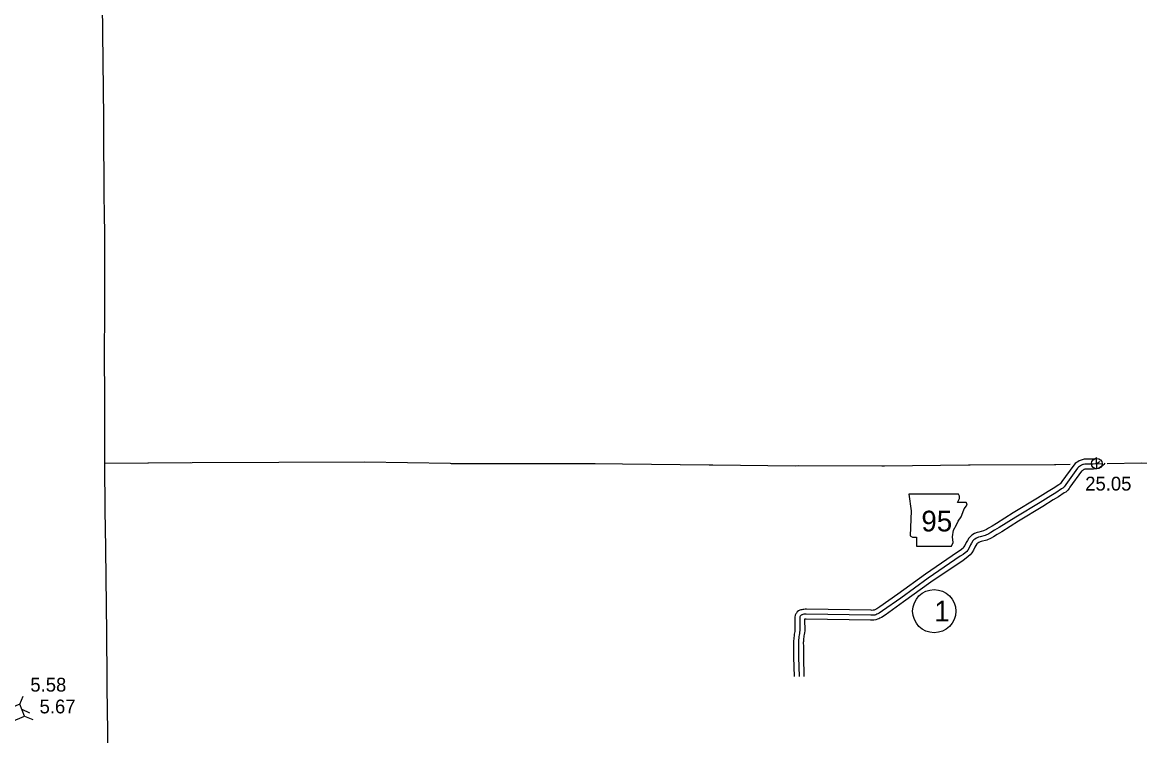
# Model space of a CAD drawing. Extents: x -83719 to 153526, y -11835 to 11446.
# Drawn here: x -664 to 475, y 2059 to 2786 of the extents above; entities that cross this region are included whole.
import ezdxf

# ---------------------------------------------------------------- set-up
doc = ezdxf.new("R2010")
doc.units = 0
for name, color, linetype in [('Level 10', 7, 'Continuous'), ('Level 2', 7, 'Continuous'), ('Level 20', 7, 'Continuous'), ('Level 21', 7, 'Continuous'), ('Level 25', 7, 'Continuous'), ('Level 26', 7, 'Continuous'), ('Level 27', 7, 'Continuous'), ('Level 58', 7, 'Continuous'), ('Level 59', 7, 'Continuous')]:
    doc.layers.add(name, color=color, linetype=linetype)

msp = doc.modelspace()

# ---------------------------------------------------------------- linework, layer by layer
at = {"layer": 'Level 10'}
for points in [[(431.4, 2342.7), (431.3, 2342.6), (431.1, 2342.3), (430.8, 2342), (430.6, 2341.8), (430.3, 2341.6), (429.8, 2341.4), (428.9, 2341), (427.4, 2340.8), (418.4, 2340.8), (416.3, 2340.3), (415.5, 2340), (414.5, 2339.6), (413.3, 2339.1), (412, 2338.3), (410.7, 2337.4), (409.3, 2336.3), (407.9, 2334.9), (395.7, 2318), (395, 2317), (394.2, 2316), (393.5, 2315.3), (392.6, 2314.7), (387, 2310.9), (381.8, 2307.9), (370.9, 2301)], [(439.6, 2336.9), (438.5, 2335.5), (437.4, 2334.5), (436.7, 2333.9), (435.4, 2333), (434.3, 2332.4), (432.3, 2331.5), (430.9, 2331.1), (427.8, 2330.8), (419.6, 2330.8), (419.2, 2330.7), (419, 2330.7), (418.5, 2330.4), (418, 2330.2), (417.3, 2329.8), (416.6, 2329.3), (415.9, 2328.8), (415.6, 2328.5), (403.9, 2312.4), (403.2, 2311.1), (401.7, 2309.3), (399.8, 2307.4), (398.1, 2306.4), (392.3, 2302.4), (387, 2299.3), (376.2, 2292.6)], [(371, 2301.1), (346.1, 2286), (329.2, 2275.3), (324.6, 2272.7), (320.8, 2270.4), (319, 2269.3), (315.7, 2267.8), (311.2, 2266.5), (309.4, 2266.1), (306.5, 2265), (304, 2263.4), (302.4, 2262), (301, 2260.5), (299.5, 2257.9), (298.3, 2256), (296.7, 2252.9), (295.6, 2251), (295, 2250.2), (292.2, 2247.9), (289.4, 2246), (256.6, 2223.6), (228.5, 2203.4), (210.2, 2190.3), (207, 2188.3), (205.8, 2187.7), (204.9, 2187.2), (204.2, 2187), (203.9, 2186.9), (203.2, 2186.8), (202.3, 2186.7), (201.3, 2186.8), (135.3, 2187.9), (133.9, 2187.9), (132.8, 2187.7), (131.8, 2187.7), (130.7, 2187.4), (129.7, 2187.2), (128.7, 2186.9), (127.4, 2186.2), (126, 2185.1), (125.1, 2184), (124.6, 2183.2), (124, 2181.8), (123.5, 2179.9), (123.5, 2178), (123.5, 2166.5), (123.4, 2165.3), (123.2, 2163.8), (122.9, 2162.3), (122.7, 2160.7), (122.5, 2158.8), (122.4, 2157.2), (122.3, 2156.1), (122.1, 2154.6), (122.1, 2152.1), (122.2, 2150.9), (122.3, 2139), (122.8, 2119.3)], [(376.2, 2292.5), (351.4, 2277.5), (334.4, 2266.8), (329.7, 2264.1), (325.9, 2261.8), (323.5, 2260.4), (319.1, 2258.4), (313.6, 2256.8), (312.3, 2256.5), (311, 2256), (309.9, 2255.4), (309.4, 2254.9), (309.1, 2254.5), (308, 2252.7), (307, 2251.1), (305.5, 2248.1), (303.9, 2245.5), (302.3, 2243.3), (298.2, 2239.8), (295, 2237.7), (262.3, 2215.4), (234.4, 2195.3), (215.7, 2182), (211.9, 2179.6), (210.3, 2178.8), (209.1, 2178.2), (207.8, 2177.6), (206, 2177), (204.1, 2176.8), (202.1, 2176.7), (200.8, 2176.8), (135.2, 2177.9), (134.4, 2177.9), (133.8, 2177.8), (133.5, 2177.8), (133.6, 2165.8), (133.3, 2163.9), (133, 2162.1), (132.8, 2160.7), (132.6, 2159.5), (132.5, 2158.1), (132.4, 2156.5), (132.3, 2155), (132.1, 2153.9), (132.1, 2152.5), (132.2, 2151.4), (132.3, 2139.2), (132.8, 2119.3)]]:
    msp.add_lwpolyline(points, dxfattribs=at)
at = {"layer": 'Level 2'}
for points in [[(-580, 2561.9), (-580.3, 2599.4), (-580.4, 2601.5), (-581, 2687.4), (-580.9, 2688.9), (-581.9, 2775.5), (-581.8, 2776.3), (-583, 2861.2), (-494.6, 2861), (-488.5, 2860.9), (-405.1, 2861.7), (-404.8, 2950.1), (-404.3, 3038.9), (-405.8, 3126.3), (-407.1, 3213), (-407.7, 3300.1), (-408, 3324.7)], [(-579.4, 2288.6), (-579.9, 2336.5), (-580, 2424.6), (-580.2, 2426.1), (-579.8, 2512.4), (-579.9, 2513.7), (-580, 2561.9)], [(-579.4, 2288.6), (-579.9, 2336.5), (-580, 2398.3)], [(-79.9, 2336), (-140.3, 2336.2), (-226.6, 2336.2), (-227.5, 2336.3), (-315.3, 2337.7), (-402.6, 2337.4), (-490.9, 2337.1), (-579.9, 2336.5)], [(-492.3, 2337.1), (-579.9, 2336.5)], [(404.3, 2335.4), (389.6, 2335.1), (388.3, 2335.2), (302.3, 2334.7), (300.5, 2334.8), (214.8, 2333.8), (212.2, 2333.8), (127, 2334), (124.3, 2333.7), (39.9, 2334.6), (36.1, 2334.7), (-52.2, 2335.7), (-79.9, 2336)], [(541.2, 2336.4), (476.8, 2336.7), (441.8, 2336)], [(-576.6, 2016.4), (-576.9, 2073.5), (-577, 2075.2), (-577.8, 2161.3), (-577.8, 2163), (-578.8, 2249), (-578.7, 2250.7), (-579.4, 2288.6)], [(-576.6, 2015.1), (-576.9, 2073.5), (-577, 2075.2), (-577.8, 2161.3), (-577.8, 2163), (-578.8, 2249), (-578.7, 2250.7), (-579.4, 2288.6)]]:
    msp.add_lwpolyline(points, dxfattribs=at)
at = {"layer": 'Level 20'}
for p, q in [((-666.6, 2091), (-663.2, 2099.2)), ((-664.5, 2085.9), (-656.5, 2082.4)), ((-661.6, 2078.8), (-653.4, 2075.5))]:
    msp.add_line(p, q, dxfattribs=at)
msp.add_lwpolyline([(-666.6, 2091), (-703.2, 2075.9), (-698.2, 2063.7), (-661.6, 2078.8)], close=True, dxfattribs=at)
at = {"layer": 'Level 21'}
msp.add_lwpolyline([(239.7, 2305.2), (242.2, 2288.3), (241.1, 2262.6), (243.3, 2261.2), (247.6, 2261.2), (247.6, 2252.2), (283.1, 2252.2), (284.8, 2255.9), (284.2, 2261.8), (285.1, 2268.5), (288.2, 2273.9), (290.1, 2277.8), (293, 2282.1), (294.6, 2286.6), (296.1, 2290.3), (298.6, 2293.4), (299.2, 2295.3), (298, 2296.7), (289.3, 2296.7), (291.3, 2300.7), (291.5, 2303.2), (290.4, 2305.2)], close=True, dxfattribs=at)
at = {"layer": 'Level 26'}
for p, q in [((425.8, 2336.2), (436.7, 2336.4)), ((431.4, 2330.9), (431.1, 2341.7))]:
    msp.add_line(p, q, dxfattribs=at)
msp.add_circle((431.3, 2336.3), 5.43, dxfattribs=at)
at = {"layer": 'Level 27'}
msp.add_circle((265.6, 2185.9), 22, dxfattribs=at)
at = {"layer": 'Level 59'}
for points in [[(434.4, 2338.5), (434.1, 2338.3), (433.7, 2337.9), (432.8, 2337.3), (432.1, 2336.9), (430.5, 2336.2), (430, 2336), (427.6, 2335.8), (419, 2335.8), (417.7, 2335.5), (417.2, 2335.3), (416.5, 2335), (415.6, 2334.6), (414.6, 2334.1), (413.7, 2333.4), (412.6, 2332.6), (411.8, 2331.7), (399.8, 2315.2), (399.1, 2314.1), (398, 2312.7), (396.7, 2311.4), (395.4, 2310.5), (389.6, 2306.7), (384.4, 2303.6), (373.6, 2296.8)], [(373.6, 2296.8), (348.7, 2281.7), (331.8, 2271.1), (327.1, 2268.4), (323.4, 2266.1), (321.2, 2264.8), (317.4, 2263.1), (312.4, 2261.7), (310.8, 2261.3), (308.7, 2260.5), (307, 2259.4), (305.9, 2258.5), (305, 2257.5), (303.7, 2255.3), (302.6, 2253.6), (301.1, 2250.5), (299.8, 2248.2), (298.7, 2246.7), (295.2, 2243.8), (292.2, 2241.9), (259.5, 2219.5), (231.5, 2199.3), (212.9, 2186.1), (209.4, 2183.9), (208.1, 2183.2), (207, 2182.7), (206, 2182.3), (205, 2182), (203.6, 2181.8), (202.2, 2181.7), (201, 2181.8), (135.2, 2182.9), (134.1, 2182.9), (133.3, 2182.8), (132.6, 2182.7), (131.8, 2182.5), (131, 2182.3), (130.6, 2182.2), (130.1, 2182), (129.5, 2181.6), (129.2, 2181.1), (129, 2180.8), (128.7, 2180.2), (128.5, 2179.2), (128.5, 2178), (128.5, 2166.2), (128.3, 2164.6), (128.1, 2163), (127.8, 2161.5), (127.6, 2160.1), (127.5, 2158.4), (127.4, 2156.8), (127.3, 2155.6), (127.1, 2154.2), (127.1, 2152.3), (127.2, 2151.2), (127.3, 2139.1), (127.8, 2119.3)]]:
    msp.add_lwpolyline(points, dxfattribs=at)

# ---------------------------------------------------------------- texts
at = {"layer": 'Level 21'}
msp.add_text('95', height=21.12, dxfattribs=at).set_placement((252.5, 2267.2))
at = {"layer": 'Level 25'}
msp.add_text('25.05', height=14.08, dxfattribs=at).set_placement((419.5, 2308.9))
at = {"layer": 'Level 27'}
msp.add_text('1', height=21.1, dxfattribs=at).set_placement((265.6, 2175.4))
at = {"layer": 'Level 58'}
for s, p in [('5.58', (-655.8, 2103.9)), ('5.67', (-646.4, 2081.7))]:
    msp.add_text(s, height=14.08, dxfattribs=at).set_placement(p)

doc.saveas('drawing.dxf')
